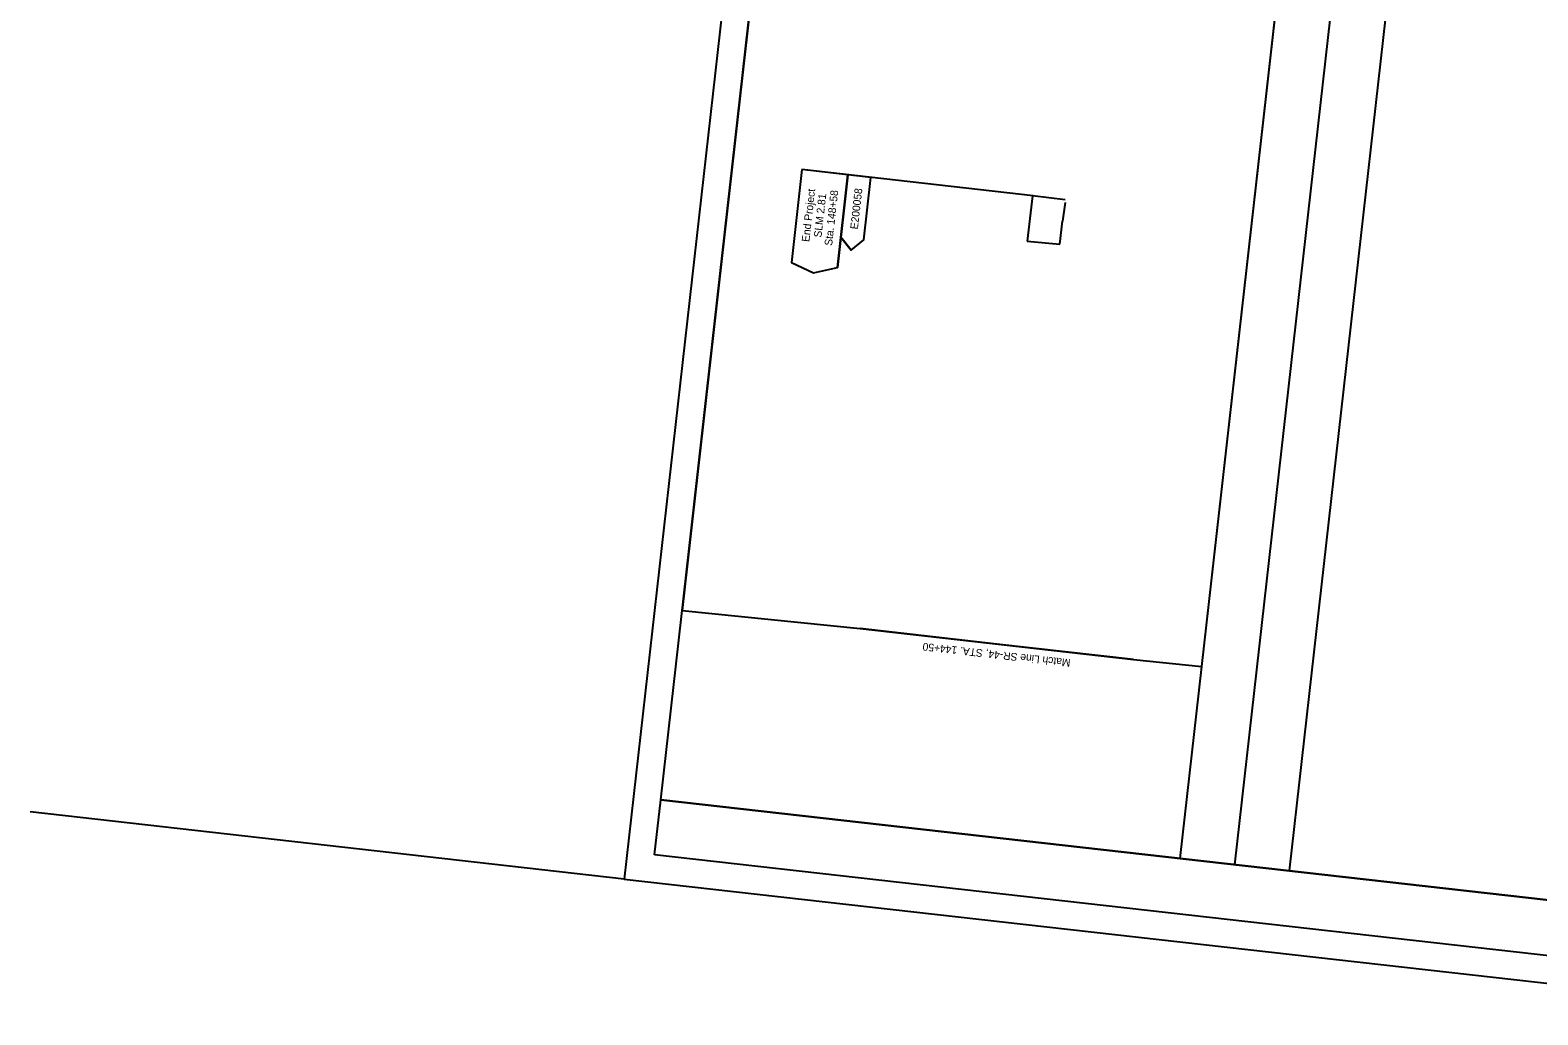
# Model space of a CAD drawing. Extents: x 2319604 to 2321967, y 627112 to 631396.
# Drawn here: x 2319795 to 2321165, y 628678 to 629572 of the extents above; entities that cross this region are included whole.
import ezdxf

# ---------------------------------------------------------------- set-up
doc = ezdxf.new("R2010")
doc.units = 0
for name, color, linetype in [('PV_P_Joint', 7, 'Continuous'), ('SC_Scratch1', 7, 'Continuous'), ('SC_Scratch2', 7, 'Continuous'), ('SC_Shading3', 7, 'Continuous'), ('SH_Border', 7, 'Continuous'), ('SH_Cut_Line', 7, 'Continuous'), ('SH_Text', 7, 'Continuous'), ('TX_P_50', 7, 'Continuous')]:
    doc.layers.add(name, color=color, linetype=linetype)

msp = doc.modelspace()

# ---------------------------------------------------------------- linework, layer by layer
at = {"layer": 'PV_P_Joint'}
for p, q in [((2320705.6, 629421.9), (2320700.7, 629380.8)), ((2320735.4, 629418.2), (2320705.6, 629421.9)), ((2320730.6, 629377.8), (2320732.9, 629398.9)), ((2320700.7, 629380.8), (2320730.6, 629377.8))]:
    msp.add_line(p, q, dxfattribs=at)
msp.add_ellipse((2321289.6, 629332.3), major_axis=(-315.3, -463.7), ratio=0.999717, start_param=5.160044, end_param=5.190378, dxfattribs=at)
at = {"layer": 'SC_Scratch1'}
for p, q in [((2320839.9, 628819.9), (2321010.9, 630335.3)), ((2320939.2, 628808.7), (2321110.3, 630324)), ((2320334.6, 628801.4), (2319794.8, 628862.4))]:
    msp.add_line(p, q, dxfattribs=at)
at = {"layer": 'SC_Scratch2'}
msp.add_lwpolyline([(2320999.9, 630238), (2320527.7, 630289.2), (2320451.6, 629615.1), (2320387.3, 629045.3), (2320549, 629028.8), (2320797.4, 629000.8), (2320859.6, 628994.4), (2320922.9, 629555.2), (2320969.7, 629970.2)], close=True, dxfattribs=at)
at = {"layer": 'SC_Shading3'}
for points in [[(2320496.1, 629445.6), (2320486.6, 629361.4), (2320506.7, 629352), (2320528.4, 629356.6), (2320537.9, 629440.9)], [(2320531.5, 629384.2), (2320540.7, 629372.5), (2320552.3, 629381.8), (2320558.7, 629438.5), (2320537.9, 629440.9)]]:
    msp.add_lwpolyline(points, close=True, dxfattribs=at)
at = {"layer": 'SH_Border'}
msp.add_line((2320889.5, 628814.3), (2321060.6, 630329.7), dxfattribs=at)
for points in [[(2320367.9, 628873.2), (2320547.3, 630463.1), (2321590.7, 630345.3), (2321411.2, 628755.4)], [(2320362.2, 628823.5), (2320367.9, 628873.2), (2321411.2, 628755.4), (2321405.6, 628705.7)]]:
    msp.add_lwpolyline(points, close=True, dxfattribs=at)
at = {"layer": 'SH_Cut_Line'}
msp.add_lwpolyline([(2321427.7, 628678.1), (2321618.4, 630367.3), (2320525.3, 630490.7), (2320334.6, 628801.4)], close=True, dxfattribs=at)
at = {"layer": 'SH_Text'}
for p, q in [((2320496.1, 629445.6), (2320486.6, 629361.4)), ((2320537.9, 629440.9), (2320528.4, 629356.6)), ((2320540.7, 629372.5), (2320531.5, 629384.2)), ((2320540.7, 629372.5), (2320552.3, 629381.8))]:
    msp.add_line(p, q, dxfattribs=at)
for points in [[(2320706.3, 629421.9), (2320496.1, 629445.6)], [(2320552.3, 629381.8), (2320558.7, 629438.5), (2320537.9, 629440.9), (2320531.5, 629384.2)], [(2320486.6, 629361.4), (2320506.7, 629352), (2320528.4, 629356.6)], [(2320797.4, 629000.8), (2320673.2, 629014.8), (2320549, 629028.8)]]:
    msp.add_lwpolyline(points, dxfattribs=at)

# ---------------------------------------------------------------- texts
for s, rotation, p in [('E200058', 83.5594, (2320546.9, 629391.1)), ('Match Line SR-44, STA. 144+50', 173.5732, (2320740.4, 629000.9))]:
    msp.add_text(s, height=7, rotation=rotation, dxfattribs=at).set_placement(p)
at = {"layer": 'TX_P_50'}
for s, p in [(' End Project', (2320502.5, 629377.1)), (' SLM 2.81', (2320513.5, 629381.1)), (' Sta. 148+58', (2320523.2, 629373.6))]:
    msp.add_text(s, height=7, rotation=83.5594, dxfattribs=at).set_placement(p)

doc.saveas('drawing.dxf')
